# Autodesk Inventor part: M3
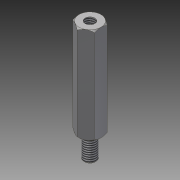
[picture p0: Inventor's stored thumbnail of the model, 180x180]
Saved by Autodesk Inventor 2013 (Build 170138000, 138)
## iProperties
Created: 2012-08
Part Number: M3
Material: Stahl
Document SubType Name: Modeling
Designer: rYan
Density: 7.85 g/cm^3
Author: rYan
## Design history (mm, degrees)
derived "Abstandsbolzen Typ B.ipt"
feature "Volumenkörper1::Abstandsbolzen Typ B.ipt"
tag "Bezeichnung1"
node "Volumenkörper1"
other parameters: "SW" = 5.5, "L" = 24, "d2" = 0, "l_" = 7, "d9" = 118 deg, "GA_" = 3, "A_" = 6, "d13" = 0, "d17" = 0.25, "d20" = 45 deg
